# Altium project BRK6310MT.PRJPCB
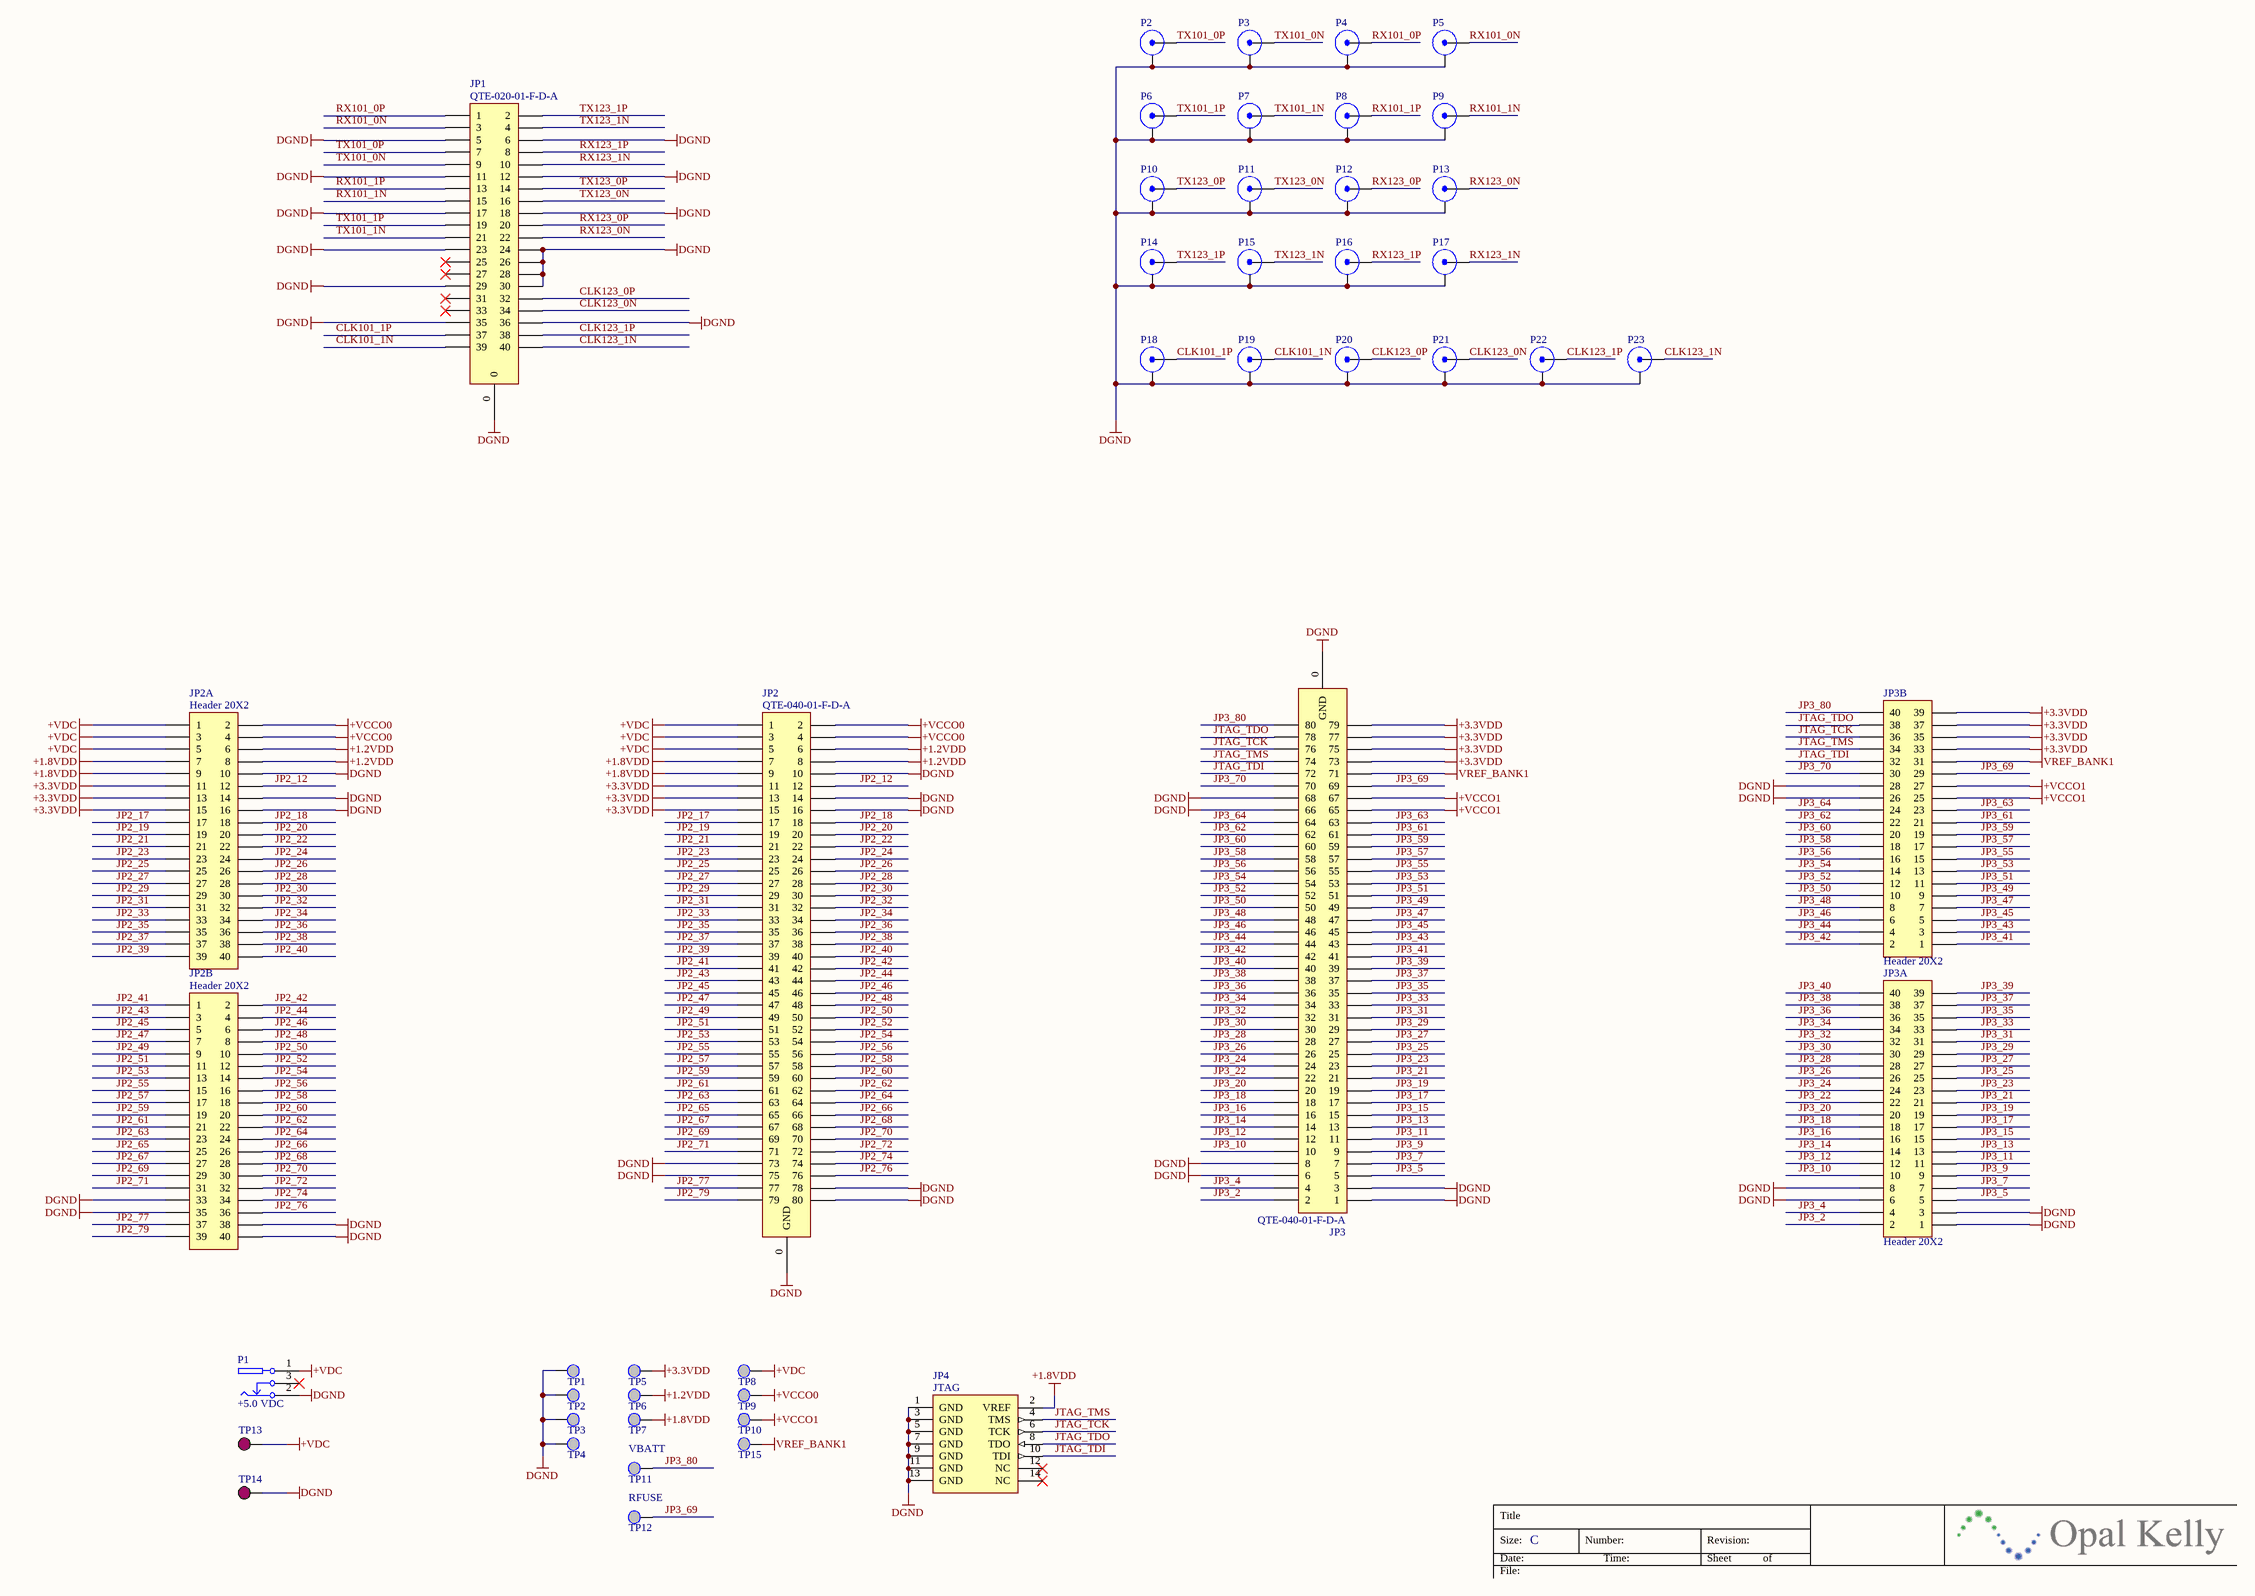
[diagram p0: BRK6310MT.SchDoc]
1 sheet, 46 parts. Net scope: global (net labels, ports and power ports of the same name join across sheets).
Board file: BRK6310MT.PcbDoc

## Sheet BRK6310MT.SchDoc: BRK6310MT
size C; Author: Jake Janovetz; Organization: Opal Kelly; Address1: 13500 SW 72nd Ave, STE 120; Address2: Portland, OR 97223; Address4: http://www.opalkelly.com; DocumentNumber: xxx; Revision: 1; SheetNumber: 1; SheetTotal: 1; PageSetup: Record=PageOptions|CenterHorizontal=True|CenterVertical=True|PrintScale=0.53|XCorrection=1.00|YCorrection=1.00|PrintKind=0|BorderSize=5000000|LeftOffset=0|BottomOffset=0|Orientation=2|PaperLength=1000|PaperWidth=1000|Scale=100|PaperSource=7|PrintQuality=-4|MediaType=1|DitherType=10|PaperKind=Letter|PrintScaleMode=1

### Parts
JP1  QTE-020-01-F-D-A  [QTE-020-01-X-D-A]
JP2  QTE-040-01-F-D-A  [QTE-040-01-X-D-A]
JP2A  Header 20X2  [HDR2X20-2MM]
JP2B  Header 20X2  [HDR2X20-2MM]
JP3  QTE-040-01-F-D-A  [QTE-040-01-X-D-A]
JP3A  Header 20X2  [HDR2X20-2MM]
JP3B  Header 20X2  [HDR2X20-2MM]
JP4  JTAG  [XILINX-JTAG]
P1  +5.0 VDC  [CUI-PJ102A]
P2  TX101_0P  [SMA]  (value not drawn)
P3  TX101_0N  [SMA]  (value not drawn)
P4  RX101_0P  [SMA]  (value not drawn)
P5  RX101_0N  [SMA]  (value not drawn)
P6  TX101_1P  [SMA]  (value not drawn)
P7  TX101_1N  [SMA]  (value not drawn)
P8  RX101_1P  [SMA]  (value not drawn)
P9  RX101_1N  [SMA]  (value not drawn)
P10  TX123_0P  [SMA]  (value not drawn)
P11  TX123_0N  [SMA]  (value not drawn)
P12  RX123_0P  [SMA]  (value not drawn)
P13  RX123_0N  [SMA]  (value not drawn)
P14  TX123_1P  [SMA]  (value not drawn)
P15  TX123_1N  [SMA]  (value not drawn)
P16  RX123_1P  [SMA]  (value not drawn)
P17  RX123_1N  [SMA]  (value not drawn)
P18  CLK101_1P  [SMA]  (value not drawn)
P19  CLK101_1N  [SMA]  (value not drawn)
P20  CLK123_0P  [SMA]  (value not drawn)
P21  CLK123_0N  [SMA]  (value not drawn)
P22  CLK123_1P  [SMA]  (value not drawn)
P23  CLK123_1N  [SMA]  (value not drawn)
TP1  DGND  [TP_MED]  (value not drawn)
TP2  DGND  [TP_MED]  (value not drawn)
TP3  DGND  [TP_MED]  (value not drawn)
TP4  DGND  [TP_MED]  (value not drawn)
TP5  +3.3VDD  [TP_MED]  (value not drawn)
TP6  +1.2VDD  [TP_MED]  (value not drawn)
TP7  +1.8VDD  [TP_MED]  (value not drawn)
TP8  +VDC  [TP_MED]  (value not drawn)
TP9  +VCCO0  [TP_MED]  (value not drawn)
TP10  +VCCO1  [TP_MED]  (value not drawn)
TP11  VBATT  [TP_MED]
TP12  RFUSE  [TP_MED]
TP13  +VDC  [POGO-PR541-1-Press-Ring-Stop]  (value not drawn)
TP14  DGND  [POGO-PR541-1-Press-Ring-Stop]  (value not drawn)
TP15  VREF_BANK1  [TP_MED]  (value not drawn)

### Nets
+1.2VDD: JP2.6 JP2.8 JP2A.6 JP2A.8 TP6.1(PIN)
+1.8VDD: JP2.7 JP2.9 JP2A.7 JP2A.9 JP4.2(VREF) TP7.1(PIN)
+3.3VDD: JP2.11 JP2.13 JP2.15 JP2A.11 JP2A.13 JP2A.15 JP3.73 JP3.75 JP3.77 JP3.79 JP3B.33 JP3B.35 JP3B.37 JP3B.39 TP5.1(PIN)
+VCCO0: JP2.2 JP2.4 JP2A.2 JP2A.4 TP9.1(PIN)
+VCCO1: JP3.65 JP3.67 JP3B.25 JP3B.27 TP10.1(PIN)
+VDC: JP2.1 JP2.3 JP2.5 JP2A.1 JP2A.3 JP2A.5 P1.1 TP8.1(PIN) TP13.1(PIN)
DGND: JP1.0 JP1.5 JP1.6 JP1.11 JP1.12 JP1.17 JP1.18 JP1.23 JP1.24 JP1.26 JP1.28 JP1.29 JP1.30 JP1.35 JP1.36 JP2.0(GND) JP2.10 JP2.14 JP2.16 JP2.73 JP2.75 JP2.78 JP2.80 JP2A.10 JP2A.14 JP2A.16 JP2B.33 JP2B.35 JP2B.38 JP2B.40 JP3.0(GND) JP3.1 JP3.3 JP3.6 JP3.8 JP3.66 JP3.68 JP3A.1 JP3A.3 JP3A.6 JP3A.8 JP3B.26 JP3B.28 JP4.1(GND) JP4.3(GND) JP4.5(GND) JP4.7(GND) JP4.9(GND) JP4.11(GND) JP4.13(GND) P1.2 P2.2(GND) P3.2(GND) P4.2(GND) P5.2(GND) P6.2(GND) P7.2(GND) P8.2(GND) P9.2(GND) P10.2(GND) P11.2(GND) P12.2(GND) P13.2(GND) P14.2(GND) P15.2(GND) P16.2(GND) P17.2(GND) P18.2(GND) P19.2(GND) P20.2(GND) P21.2(GND) P22.2(GND) P23.2(GND) TP1.1(PIN) TP2.1(PIN) TP3.1(PIN) TP4.1(PIN) TP14.1(PIN)
VREF_BANK1: JP3.71 JP3B.31 TP15.1(PIN)
CLK101_1N: JP1.39 P19.1(SIGNAL)
CLK101_1P: JP1.37 P18.1(SIGNAL)
CLK123_0N: JP1.34 P21.1(SIGNAL)
CLK123_0P: JP1.32 P20.1(SIGNAL)
CLK123_1N: JP1.40 P23.1(SIGNAL)
CLK123_1P: JP1.38 P22.1(SIGNAL)
JP2_12: JP2.12 JP2A.12
JP2_17: JP2.17 JP2A.17
JP2_18: JP2.18 JP2A.18
JP2_19: JP2.19 JP2A.19
JP2_20: JP2.20 JP2A.20
JP2_21: JP2.21 JP2A.21
JP2_22: JP2.22 JP2A.22
JP2_23: JP2.23 JP2A.23
JP2_24: JP2.24 JP2A.24
JP2_25: JP2.25 JP2A.25
JP2_26: JP2.26 JP2A.26
JP2_27: JP2.27 JP2A.27
JP2_28: JP2.28 JP2A.28
JP2_29: JP2.29 JP2A.29
JP2_30: JP2.30 JP2A.30
JP2_31: JP2.31 JP2A.31
JP2_32: JP2.32 JP2A.32
JP2_33: JP2.33 JP2A.33
JP2_34: JP2.34 JP2A.34
JP2_35: JP2.35 JP2A.35
JP2_36: JP2.36 JP2A.36
JP2_37: JP2.37 JP2A.37
JP2_38: JP2.38 JP2A.38
JP2_39: JP2.39 JP2A.39
JP2_40: JP2.40 JP2A.40
JP2_41: JP2.41 JP2B.1
JP2_42: JP2.42 JP2B.2
JP2_43: JP2.43 JP2B.3
JP2_44: JP2.44 JP2B.4
JP2_45: JP2.45 JP2B.5
JP2_46: JP2.46 JP2B.6
JP2_47: JP2.47 JP2B.7
JP2_48: JP2.48 JP2B.8
JP2_49: JP2.49 JP2B.9
JP2_50: JP2.50 JP2B.10
JP2_51: JP2.51 JP2B.11
JP2_52: JP2.52 JP2B.12
JP2_53: JP2.53 JP2B.13
JP2_54: JP2.54 JP2B.14
JP2_55: JP2.55 JP2B.15
JP2_56: JP2.56 JP2B.16
JP2_57: JP2.57 JP2B.17
JP2_58: JP2.58 JP2B.18
JP2_59: JP2.59 JP2B.19
JP2_60: JP2.60 JP2B.20
JP2_61: JP2.61 JP2B.21
JP2_62: JP2.62 JP2B.22
JP2_63: JP2.63 JP2B.23
JP2_64: JP2.64 JP2B.24
JP2_65: JP2.65 JP2B.25
JP2_66: JP2.66 JP2B.26
JP2_67: JP2.67 JP2B.27
JP2_68: JP2.68 JP2B.28
JP2_69: JP2.69 JP2B.29
JP2_70: JP2.70 JP2B.30
JP2_71: JP2.71 JP2B.31
JP2_72: JP2.72 JP2B.32
JP2_74: JP2.74 JP2B.34
JP2_76: JP2.76 JP2B.36
JP2_77: JP2.77 JP2B.37
JP2_79: JP2.79 JP2B.39
JP3_2: JP3.2 JP3A.2
JP3_4: JP3.4 JP3A.4
JP3_5: JP3.5 JP3A.5
JP3_7: JP3.7 JP3A.7
JP3_9: JP3.9 JP3A.9
JP3_10: JP3.10 JP3A.10
JP3_11: JP3.11 JP3A.11
JP3_12: JP3.12 JP3A.12
JP3_13: JP3.13 JP3A.13
JP3_14: JP3.14 JP3A.14
JP3_15: JP3.15 JP3A.15
JP3_16: JP3.16 JP3A.16
JP3_17: JP3.17 JP3A.17
JP3_18: JP3.18 JP3A.18
JP3_19: JP3.19 JP3A.19
JP3_20: JP3.20 JP3A.20
JP3_21: JP3.21 JP3A.21
JP3_22: JP3.22 JP3A.22
JP3_23: JP3.23 JP3A.23
JP3_24: JP3.24 JP3A.24
JP3_25: JP3.25 JP3A.25
JP3_26: JP3.26 JP3A.26
JP3_27: JP3.27 JP3A.27
JP3_28: JP3.28 JP3A.28
JP3_29: JP3.29 JP3A.29
JP3_30: JP3.30 JP3A.30
JP3_31: JP3.31 JP3A.31
JP3_32: JP3.32 JP3A.32
JP3_33: JP3.33 JP3A.33
JP3_34: JP3.34 JP3A.34
JP3_35: JP3.35 JP3A.35
JP3_36: JP3.36 JP3A.36
JP3_37: JP3.37 JP3A.37
JP3_38: JP3.38 JP3A.38
JP3_39: JP3.39 JP3A.39
JP3_40: JP3.40 JP3A.40
JP3_41: JP3.41 JP3B.1
JP3_42: JP3.42 JP3B.2
JP3_43: JP3.43 JP3B.3
JP3_44: JP3.44 JP3B.4
JP3_45: JP3.45 JP3B.5
JP3_46: JP3.46 JP3B.6
JP3_47: JP3.47 JP3B.7
JP3_48: JP3.48 JP3B.8
JP3_49: JP3.49 JP3B.9
JP3_50: JP3.50 JP3B.10
JP3_51: JP3.51 JP3B.11
JP3_52: JP3.52 JP3B.12
JP3_53: JP3.53 JP3B.13
JP3_54: JP3.54 JP3B.14
JP3_55: JP3.55 JP3B.15
JP3_56: JP3.56 JP3B.16
JP3_57: JP3.57 JP3B.17
JP3_58: JP3.58 JP3B.18
JP3_59: JP3.59 JP3B.19
JP3_60: JP3.60 JP3B.20
JP3_61: JP3.61 JP3B.21
JP3_62: JP3.62 JP3B.22
JP3_63: JP3.63 JP3B.23
JP3_64: JP3.64 JP3B.24
JP3_69: JP3.69 JP3B.29 TP12.1(PIN)
JP3_70: JP3.70 JP3B.30
JP3_80: JP3.80 JP3B.40 TP11.1(PIN)
JTAG_TCK: JP3.76 JP3B.36 JP4.6(TCK)
JTAG_TDI: JP3.72 JP3B.32 JP4.10(TDI)
JTAG_TDO: JP3.78 JP3B.38 JP4.8(TDO)
JTAG_TMS: JP3.74 JP3B.34 JP4.4(TMS)
RX101_0N: JP1.3 P5.1(SIGNAL)
RX101_0P: JP1.1 P4.1(SIGNAL)
RX101_1N: JP1.15 P9.1(SIGNAL)
RX101_1P: JP1.13 P8.1(SIGNAL)
RX123_0N: JP1.22 P13.1(SIGNAL)
RX123_0P: JP1.20 P12.1(SIGNAL)
RX123_1N: JP1.10 P17.1(SIGNAL)
RX123_1P: JP1.8 P16.1(SIGNAL)
TX101_0N: JP1.9 P3.1(SIGNAL)
TX101_0P: JP1.7 P2.1(SIGNAL)
TX101_1N: JP1.21 P7.1(SIGNAL)
TX101_1P: JP1.19 P6.1(SIGNAL)
TX123_0N: JP1.16 P11.1(SIGNAL)
TX123_0P: JP1.14 P10.1(SIGNAL)
TX123_1N: JP1.4 P15.1(SIGNAL)
TX123_1P: JP1.2 P14.1(SIGNAL)

Not connected (* = marked no-connect by the designer): JP1 25* 27* 31* 33*; JP4 12(NC)* 14(NC)*; P1 3*

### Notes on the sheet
- Title
- Size:
- Date:
- File:
- C
- Number:
- Time:
- Revision:
- Sheet
- of

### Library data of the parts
JP1 = 000973: 0.8mm hi-speed, high-density header (female); Manufacturer: Samtec; partnumber: 000973; Description 2: 40-pin, ground protection in middle
JP2 JP3 = 000972: 0.8mm hi-speed, high-density header (female); Manufacturer: Samtec; partnumber: 000972; Description 2: 80-pin, ground protection in middle
JP2A JP2B JP3A JP3B = Header 20X2: Header, 20-Pin, Dual row; Manufacturer: Generic Components; Class I: Connector
JP4 = 000541: 2mm header, shrouded; Manufacturer: Molex; Manufacturer_PN: 87831-1420; partnumber: 000541; Description 2: Dual-row, 14-pos, Xilinx JTAG compatible
P1 = DCPOWER: DC Power Connector; Manufacturer: CUI, Inc.; PartNumber: 000038
P2-P23 = 000974: Straight SMA PCB Mount; Manufacturer: Amphenol; PartNumber: 000974; Manufacturer_PN: 901-144-8RFX; Class I: Connector; Class II: RF Coaxial
TP1-TP12 TP15 = TESTPOINT: PartNumber: 000042
TP13 TP14 = 000768: Pogo Pin Socket; Manufacturer: Everett Charles Technologies; Manufacturer_PN: PR541-1; partnumber: 000768; Description 2: TEST SPRING SOCKET, PCB, SOLDER -1.47mm x 23.62mm - 1.78mm Press Ring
